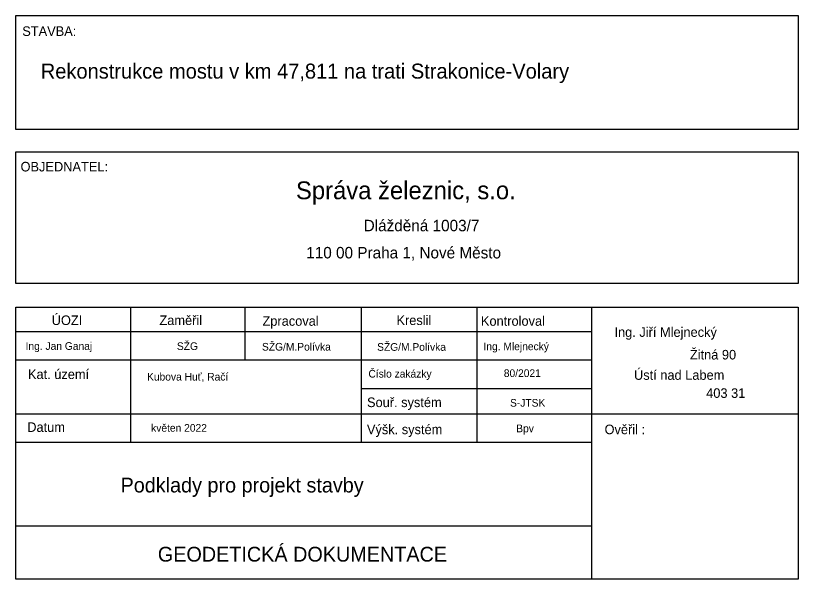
# Model space of a CAD drawing. Extents: x -879530 to -879371, y -1019242 to -1019127.
import ezdxf

# ---------------------------------------------------------------- set-up
doc = ezdxf.new("R2010")
doc.units = 0
doc.layers.add('tabulka', color=7, linetype='Continuous')

msp = doc.modelspace()

# ---------------------------------------------------------------- linework, layer by layer
at = {"layer": 'tabulka'}
for p, q in [((-879530.09, -1019186.45), (-879371.44, -1019186.45)), ((-879506.8, -1019186.45), (-879506.8, -1019213.77)), ((-879483.66, -1019186.45), (-879483.66, -1019197.07)), ((-879460.06, -1019186.45), (-879460.06, -1019213.77)), ((-879436.61, -1019186.45), (-879436.61, -1019213.77)), ((-879413.31, -1019241.58), (-879413.31, -1019186.45)), ((-879530.09, -1019191.36), (-879413.31, -1019191.36)), ((-879530.09, -1019197.07), (-879413.31, -1019197.07)), ((-879460.06, -1019202.88), (-879413.31, -1019202.88)), ((-879530.09, -1019208.07), (-879371.44, -1019208.07)), ((-879530.09, -1019213.77), (-879413.31, -1019213.77)), ((-879530.09, -1019230.76), (-879413.31, -1019230.76))]:
    msp.add_line(p, q, dxfattribs=at)
for points in [[(-879530.09, -1019127.36), (-879371.44, -1019127.36), (-879371.44, -1019150.43), (-879530.09, -1019150.43)], [(-879530.09, -1019154.95), (-879371.44, -1019154.95), (-879371.44, -1019181.64), (-879530.09, -1019181.64)]]:
    msp.add_lwpolyline(points, close=True, dxfattribs=at)
msp.add_lwpolyline([(-879371.44, -1019186.45), (-879371.44, -1019241.58), (-879530.09, -1019241.58), (-879530.09, -1019186.45)], dxfattribs=at)

# ---------------------------------------------------------------- texts
for s, height, p in [('STAVBA:', 1.94, (-879528.75, -1019131.47)), ('Rekonstrukce mostu v km 47,811 na trati Strakonice-Volary', 3.04, (-879525, -1019140.12)), ('OBJEDNATEL:', 1.94, (-879529.1, -1019158.93)), ('Správa železnic, s.o.', 3.61, (-879473.27, -1019164.56)), ('Dlážděná 1003/7', 2.32, (-879459.55, -1019171.05)), ('110 00 Praha 1, Nové Město', 2.32, (-879471.19, -1019176.55)), ('ÚOZI', 1.94, (-879522.79, -1019190.05)), ('Zaměřil', 1.94, (-879500.95, -1019190.05)), ('Zpracoval', 1.94, (-879480.06, -1019190.2)), ('Kreslil', 1.94, (-879452.9, -1019190.05)), ('Kontroloval', 1.94, (-879435.78, -1019190.2)), ('Ing. Jiří Mlejnecký', 1.94, (-879408.71, -1019192.45)), ('Ing. Jan Ganaj', 1.552, (-879528.08, -1019195.08)), ('SŽG', 1.552, (-879497.41, -1019195.11)), ('SŽG/M.Polívka', 1.552, (-879480.16, -1019195.23)), ('SŽG/M.Polívka', 1.552, (-879456.82, -1019195.27)), ('Ing. Mlejnecký', 1.552, (-879435.26, -1019195.15)), ('Žitná 90', 1.94, (-879393.42, -1019197.03)), ('Kat. území', 1.94, (-879527.6, -1019200.99)), ('Kubova Huť, Račí', 1.552, (-879503.46, -1019201.3)), ('Číslo zakázky', 1.552, (-879458.58, -1019200.7)), ('80/2021', 1.552, (-879431.14, -1019200.58)), ('Ústí nad Labem', 1.94, (-879404.75, -1019201.15)), ('403 31', 1.94, (-879390.12, -1019204.81)), ('Souř. systém', 1.94, (-879458.87, -1019206.68)), ('S-JTSK', 1.552, (-879429.88, -1019206.59)), ('Datum', 1.94, (-879527.74, -1019211.71)), ('květen 2022', 1.552, (-879502.63, -1019211.67)), ('Výšk. systém', 1.94, (-879458.89, -1019212.17)), ('Bpv', 1.552, (-879428.62, -1019211.78)), ('Ověřil :', 1.94, (-879410.72, -1019212.17)), ('Podklady pro projekt stavby', 3, (-879508.83, -1019223.98)), ('GEODETICKÁ DOKUMENTACE ', 3, (-879501.27, -1019237.99))]:
    msp.add_text(s, height=height, dxfattribs=at).set_placement(p)

doc.saveas('drawing.dxf')
